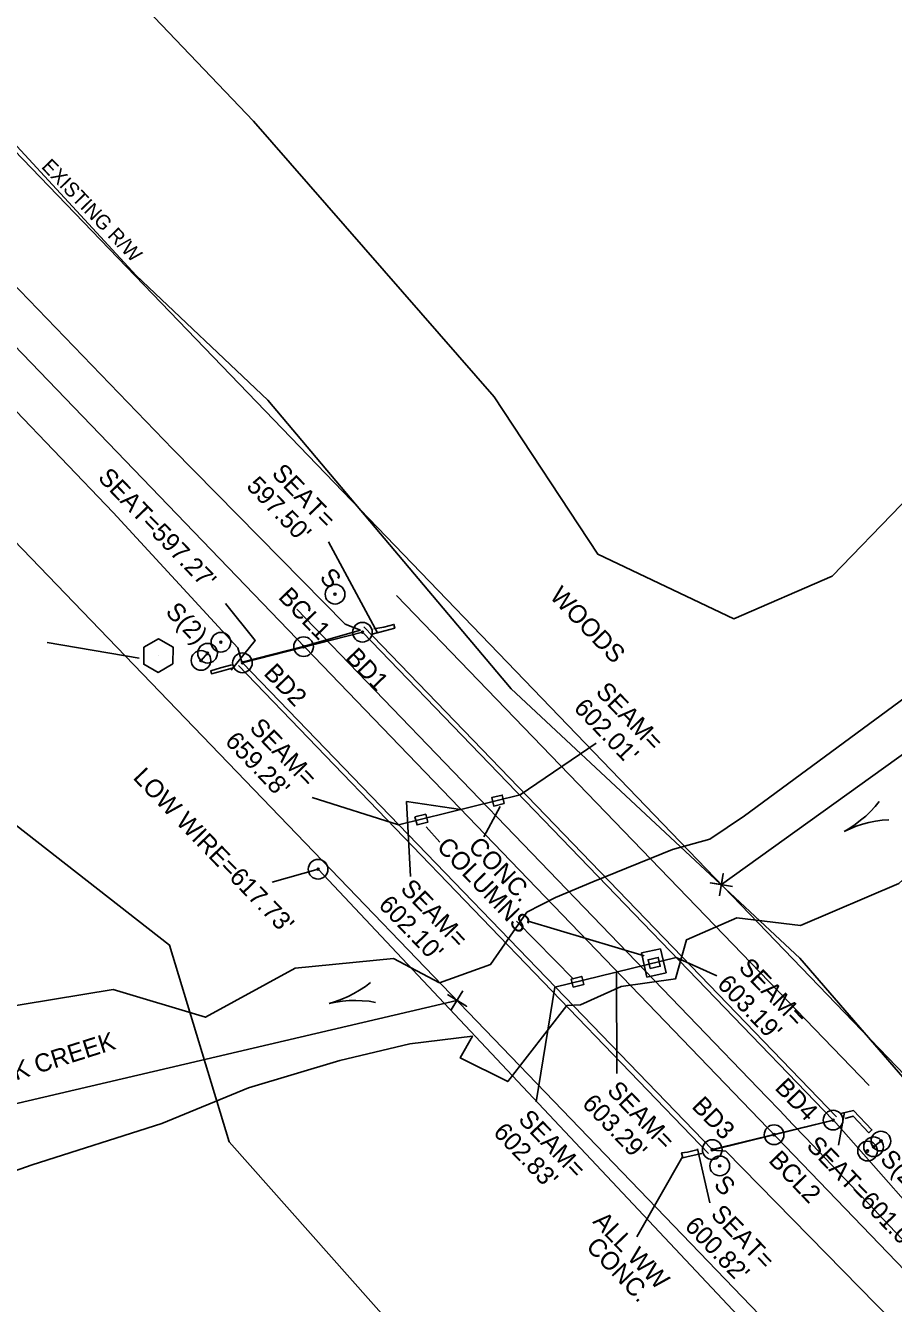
# Model space of a CAD drawing. Extents: x 1650735 to 1651711, y 679647 to 680525.
# Drawn here: x 1651160.8 to 1651353.2, y 680017 to 680300.3 of the extents above; entities that cross this region are included whole.
import ezdxf

# ---------------------------------------------------------------- set-up
doc = ezdxf.new("R2010")
doc.units = 0
for name, color, linetype in [('CTL Supplemental Horizontal and Vertical Leader', 7, 'Continuous'), ('Exist Horizontal Alignment', 7, 'Continuous'), ('Exist Hydro Jurisdictional Stream or Body of Water Mitigable Text', 7, 'Continuous'), ('Exist Hydro Stream Flow Arrow CELL', 7, 'Continuous'), ('Exist Hydro Stream or Body of Water', 7, 'Continuous'), ('Exist Hydro Stream or Body of Water Text', 7, 'Continuous'), ('Exist Other Culture Located Object CELL', 7, 'Continuous'), ('Exist Other Culture Located Object Leader', 7, 'Continuous'), ('Exist Other Culture Located Object Text', 7, 'Continuous'), ('Exist Other Culture Sign CELL', 7, 'Continuous'), ('Exist Other Culture Sign Text', 7, 'Continuous'), ('Exist Property Corner CELL', 7, 'Continuous'), ('Exist Property Line', 7, 'Continuous'), ('Exist Right of Way Line', 7, 'Continuous'), ('Exist Right of Way Line Text', 7, 'Continuous'), ('Exist Roads EOP', 7, 'Continuous'), ('Exist Roads EOP Other', 7, 'Continuous'), ('Exist Roads EOP Other Leader', 7, 'Continuous'), ('Exist Roads EOP Other Text', 7, 'Continuous'), ('Exist Structure Major Bridge Seam', 7, 'Continuous'), ('Exist Structure Major Bridge Seat Top Elevation', 7, 'Continuous'), ('Exist Structure Major Bridge WW', 7, 'Continuous'), ('Exist Structure Major Bridge WW Leader', 7, 'Continuous'), ('Exist Structure Major Bridge WW Text', 7, 'Continuous'), ('Exist Structure Major Deck Tunnel Box Culvert', 7, 'Continuous'), ('Exist Utilities Other Located Object CELL', 7, 'Continuous'), ('Exist Utilities Other Located Object Leader', 7, 'Continuous'), ('Exist Utilities Other Located Object Text', 7, 'Continuous'), ('Exist Utilities Power Pole Text', 7, 'Continuous'), ('Exist Vegetation Woods Line', 7, 'Continuous'), ('Exist Vegetation Woods Line Text', 7, 'Continuous')]:
    doc.layers.add(name, color=color, linetype=linetype)

msp = doc.modelspace()

# ---------------------------------------------------------------- linework, layer by layer
at = {"layer": 'CTL Supplemental Horizontal and Vertical Leader'}
msp.add_lwpolyline([(1651186.04, 680160.03), (1651165.62, 680163.51)], dxfattribs=at)
at = {"layer": 'Exist Horizontal Alignment'}
msp.add_line((1651012.3, 680380.99), (1651537.82, 679835.25), dxfattribs=at)
at = {"layer": 'Exist Hydro Jurisdictional Stream or Body of Water Mitigable Text'}
msp.add_line((1651190.29, 680160.59), (1651190.29, 680160.59), dxfattribs=at)
msp.add_lwpolyline([(1651187.06, 680162.47), (1651190.31, 680164.28), (1651193.56, 680162.49), (1651193.51, 680158.77), (1651190.26, 680156.88), (1651187.06, 680158.69)], close=True, dxfattribs=at)
at = {"layer": 'Exist Hydro Stream Flow Arrow CELL'}
for p, q in [((1651346.69, 680123.93), (1651346.69, 680123.93)), ((1651233.02, 680084.71), (1651233.02, 680084.71))]:
    msp.add_line(p, q, dxfattribs=at)
for points in [[(1651350.08, 680128.26), (1651349.17, 680127.11), (1651348.11, 680126.04), (1651347.06, 680125), (1651345.95, 680124.08), (1651344.76, 680123.19), (1651343.52, 680122.36), (1651342.26, 680121.62)], [(1651352.18, 680124.2), (1651350.72, 680124.12), (1651349.24, 680123.87), (1651347.79, 680123.61), (1651346.39, 680123.23), (1651344.98, 680122.77), (1651343.59, 680122.23), (1651342.26, 680121.62)], [(1651237.32, 680088.15), (1651236.17, 680087.24), (1651234.9, 680086.44), (1651233.63, 680085.68), (1651232.34, 680085.03), (1651230.98, 680084.45), (1651229.57, 680083.93), (1651228.17, 680083.5)], [(1651238.43, 680083.71), (1651236.99, 680083.96), (1651235.49, 680084.07), (1651234.02, 680084.15), (1651232.57, 680084.11), (1651231.09, 680083.99), (1651229.61, 680083.78), (1651228.17, 680083.5)]]:
    msp.add_lwpolyline(points, dxfattribs=at)
at = {"layer": 'Exist Hydro Stream or Body of Water'}
for points in [[(1651362.87, 680156.49), (1651320.19, 680125.07), (1651312.51, 680119.91), (1651304.26, 680117.62), (1651286.56, 680110.48), (1651278.28, 680106.96), (1651271.94, 680103.7)], [(1651409.21, 680154.78), (1651408.26, 680151.68), (1651378.34, 680131.92), (1651354.44, 680110.09), (1651332.62, 680100.74), (1651318.49, 680102.45), (1651307.34, 680097.61), (1651304.94, 680088.95), (1651292.83, 680087.22), (1651283.85, 680083.18)], [(1651271.94, 680103.7), (1651263.94, 680092.12), (1651252.63, 680088.06), (1651242.37, 680093.46), (1651220.61, 680091.28), (1651200.71, 680080.43), (1651180.24, 680086.55), (1651153.32, 680082.11), (1651107.96, 680068.84), (1651070.16, 680055.36)], [(1651283.85, 680083.18), (1651280.79, 680083.02), (1651267.73, 680066.16), (1651257.19, 680071.42), (1651259.9, 680076.25), (1651246.03, 680074.54), (1651230.51, 680070.83), (1651210.23, 680064.78), (1651191.09, 680056.85), (1651162.29, 680047.74), (1651122.74, 680033.79), (1651076.83, 680019.72)]]:
    msp.add_lwpolyline(points, dxfattribs=at)
at = {"layer": 'Exist Other Culture Located Object CELL'}
for centre, radius in [((1651235.53, 680165.78), 2.18), ((1651235.53, 680165.78), 0.24), ((1651222.46, 680162.57), 2.18), ((1651208.93, 680158.99), 2.18), ((1651222.46, 680162.57), 0.24), ((1651208.93, 680158.99), 0.24), ((1651339.85, 680057.63), 2.18), ((1651326.76, 680054.39), 2.18), ((1651339.85, 680057.63), 0.24), ((1651313.05, 680051.09), 2.18), ((1651326.76, 680054.39), 0.24), ((1651313.05, 680051.09), 0.24)]:
    msp.add_circle(centre, radius, dxfattribs=at)
at = {"layer": 'Exist Other Culture Located Object Leader'}
for p, q in [((1651238.86, 680165.65), (1651228.01, 680185.84)), ((1651270.45, 680129.72), (1651287.34, 680141.19)), ((1651243.5, 680123.07), (1651224.41, 680129.12)), ((1651305.09, 680093.68), (1651314.04, 680089.63)), ((1651291.85, 680090.48), (1651291.93, 680067.97)), ((1651278.14, 680087.13), (1651274, 680061.65)), ((1651342.37, 680059.38), (1651341.06, 680052.05)), ((1651309.76, 680051.24), (1651312.53, 680039.27))]:
    msp.add_line(p, q, dxfattribs=at)
for points in [[(1651206.42, 680157.39), (1651211.71, 680163.92), (1651205.16, 680172.13)], [(1651257.23, 680126.48), (1651245.29, 680128.24), (1651246.19, 680111.61)]]:
    msp.add_lwpolyline(points, dxfattribs=at)
at = {"layer": 'Exist Other Culture Sign CELL'}
for p, q in [((1651201.19, 680161.11), (1651199.74, 680159.51)), ((1651350.44, 680052.98), (1651348.8, 680051.71))]:
    msp.add_line(p, q, dxfattribs=at)
for centre, radius in [((1651229.45, 680174.21), 2.18), ((1651229.45, 680174.21), 0.24), ((1651204.14, 680163.56), 2.18), ((1651201.19, 680161.11), 2.18), ((1651204.14, 680163.56), 0.24), ((1651199.74, 680159.51), 2.18), ((1651201.19, 680161.11), 0.24), ((1651199.74, 680159.51), 0.24), ((1651347.48, 680050.77), 2.18), ((1651348.8, 680051.71), 2.18), ((1651350.44, 680052.98), 2.18), ((1651350.44, 680052.98), 0.24), ((1651314.71, 680047.49), 2.18), ((1651347.48, 680050.77), 0.24), ((1651348.8, 680051.71), 0.24), ((1651314.71, 680047.49), 0.24)]:
    msp.add_circle(centre, radius, dxfattribs=at)
at = {"layer": 'Exist Property Corner CELL'}
for p, q in [((1651315.07, 680109.82), (1651315.07, 680109.82)), ((1651256.47, 680084.17), (1651256.47, 680084.17))]:
    msp.add_line(p, q, dxfattribs=at)
for points in [[(1651314.67, 680107.35), (1651315.48, 680112.29), (1651315.07, 680109.82), (1651312.6, 680110.22), (1651317.54, 680109.42)], [(1651257.79, 680086.3), (1651255.15, 680082.05), (1651256.47, 680084.17), (1651258.6, 680082.86), (1651254.35, 680085.49)]]:
    msp.add_lwpolyline(points, dxfattribs=at)
at = {"layer": 'Exist Property Line'}
for p, q in [((1651599.36, 680314.21), (1651315.07, 680109.82)), ((1650934.59, 680008.86), (1651256.47, 680084.17))]:
    msp.add_line(p, q, dxfattribs=at)
at = {"layer": 'Exist Right of Way Line'}
for p, q in [((1651033.91, 680401.8), (1651559.43, 679856.06)), ((1650990.69, 680360.18), (1651516.21, 679814.44))]:
    msp.add_line(p, q, dxfattribs=at)
at = {"layer": 'Exist Roads EOP'}
for points in [[(1651019.58, 680387.57), (1651056.5, 680349), (1651091.07, 680312.89), (1651125.44, 680277.26), (1651159.55, 680241.49), (1651193.48, 680206.33), (1651231.7, 680167.56), (1651235.09, 680166.23)], [(1651005.03, 680374.4), (1651042.33, 680335.37), (1651077.42, 680299.13), (1651111.45, 680263.82), (1651145.42, 680228.7), (1651180.3, 680192.34), (1651207.92, 680162.35), (1651208.79, 680159.11)], [(1651208.79, 680159.11), (1651222.37, 680162.64), (1651235.09, 680166.23)], [(1651312.95, 680050.96), (1651326.69, 680054.39), (1651339.94, 680057.61)], [(1651339.94, 680057.61), (1651367.05, 680026.88), (1651401.64, 679990.76), (1651436.66, 679954.64), (1651471.24, 679919), (1651505.26, 679883.18), (1651544.65, 679842.12)], [(1651312.95, 680050.96), (1651316.09, 680050.72), (1651353.1, 680012.96), (1651388.04, 679976.97), (1651422.2, 679940.73), (1651457.05, 679905.32), (1651491.83, 679868.95), (1651530.99, 679828.38)]]:
    msp.add_lwpolyline(points, dxfattribs=at)
at = {"layer": 'Exist Roads EOP Other'}
for points in [[(1651266.93, 680127.79), (1651264.62, 680127.25), (1651264.18, 680129.12), (1651266.49, 680129.66)], [(1651247.16, 680124.83), (1651247.62, 680123.05), (1651250, 680123.66), (1651249.54, 680125.44)], [(1651301.61, 680095.63), (1651297.39, 680094.69), (1651298.58, 680089.35), (1651302.81, 680090.3)], [(1651299.27, 680091.23), (1651298.82, 680093.16), (1651301.09, 680093.69), (1651301.54, 680091.75)], [(1651282.23, 680087.07), (1651281.78, 680088.87), (1651284.14, 680089.47), (1651284.59, 680087.67)]]:
    msp.add_lwpolyline(points, close=True, dxfattribs=at)
at = {"layer": 'Exist Roads EOP Other Leader'}
for p, q in [((1651266.06, 680127.17), (1651262.43, 680120.43)), ((1651249.61, 680122.67), (1651252.65, 680119.27)), ((1651282.3, 680088.89), (1651269.64, 680101.71)), ((1651297.99, 680094.02), (1651272.27, 680101.72))]:
    msp.add_line(p, q, dxfattribs=at)
at = {"layer": 'Exist Structure Major Bridge Seam'}
for p, q in [((1651270.45, 680129.72), (1651243.5, 680123.07)), ((1651305.09, 680093.68), (1651278.14, 680087.13))]:
    msp.add_line(p, q, dxfattribs=at)
at = {"layer": 'Exist Structure Major Bridge WW'}
for points in [[(1651237.38, 680165.26), (1651240.51, 680166.07), (1651242.69, 680166.68), (1651242.5, 680167.51), (1651240.24, 680166.93), (1651238.03, 680166.49)], [(1651206.89, 680157.85), (1651204.26, 680157.13), (1651202.04, 680156.58), (1651201.89, 680157.21), (1651204.04, 680157.9), (1651206.6, 680158.55)], [(1651341.53, 680059.07), (1651344.39, 680059.74), (1651348.44, 680055.45), (1651347.76, 680054.83), (1651344.31, 680058.52), (1651342.55, 680058.01)], [(1651309.91, 680051.15), (1651307.58, 680050.55), (1651306.27, 680050.34), (1651306.5, 680049.28), (1651307.73, 680049.59), (1651310.73, 680050.23)]]:
    msp.add_lwpolyline(points, dxfattribs=at)
at = {"layer": 'Exist Structure Major Bridge WW Leader'}
msp.add_line((1651306.55, 680049.66), (1651296.35, 680031.79), dxfattribs=at)
at = {"layer": 'Exist Structure Major Deck Tunnel Box Culvert'}
msp.add_lwpolyline([(1651208.93, 680158.99), (1651313.05, 680051.09), (1651339.85, 680057.63), (1651235.53, 680165.78)], close=True, dxfattribs=at)
at = {"layer": 'Exist Utilities Other Located Object CELL'}
for radius in [2.18, 0.24]:
    msp.add_circle((1651225.7, 680113.25), radius, dxfattribs=at)
at = {"layer": 'Exist Utilities Other Located Object Leader'}
msp.add_line((1651225.7, 680113.25), (1651215.53, 680110.38), dxfattribs=at)
at = {"layer": 'Exist Utilities Power Pole Text'}
for p, q in [((1651347.81, 680065.31), (1651243.05, 680173.91)), ((1651221, 680170.86), (1651325.15, 680062.71)), ((1651340.61, 680058.37), (1651235.85, 680166.97)), ((1651208.03, 680158.38), (1651312.19, 680050.23)), ((1651225.7, 680113.25), (1651328.23, 680004.23))]:
    msp.add_line(p, q, dxfattribs=at)
msp.add_arc((1644826.06, 673836.82), 9000, 42.083008, 43.770098, dxfattribs=at)
at = {"layer": 'Exist Vegetation Woods Line'}
msp.add_line((1651332.44, 680093.53), (1651268.45, 680153.23), dxfattribs=at)
for points in [[(1651060.47, 680427.14), (1651110.65, 680381.51), (1651170.59, 680321.84), (1651211.4, 680279.05), (1651264.74, 680217.96)], [(1651268.45, 680153.23), (1651214.56, 680217.23), (1651185.34, 680244.85), (1651142.06, 680291.73), (1651110.43, 680323.33), (1651070.3, 680366.4), (1651038.41, 680400.33)], [(1650967.81, 680302.13), (1650989.98, 680311.82), (1651003.7, 680297.93), (1651028.47, 680259.93), (1651064.77, 680218.76), (1651095.8, 680179.69), (1651142.63, 680135.48), (1651192.79, 680096.42), (1651205.99, 680052.81)], [(1651264.74, 680217.96), (1651287.7, 680183.05), (1651317.85, 680168.78), (1651339.66, 680178.23), (1651416.09, 680257.26)], [(1651533.77, 680151.79), (1651500.2, 680143.28), (1651448.94, 680108.35), (1651428.64, 680087.41), (1651415.56, 680062.68), (1651389.29, 680041.87), (1651370.95, 680049.08), (1651332.44, 680093.53)], [(1651205.99, 680052.81), (1651250.75, 680002.32), (1651325.09, 679941.65), (1651395.44, 679858.06), (1651436.98, 679824.06), (1651426.61, 679814.61)]]:
    msp.add_lwpolyline(points, dxfattribs=at)

# ---------------------------------------------------------------- texts
at = {"layer": 'Exist Hydro Stream or Body of Water Text'}
msp.add_text('LICK CREEK', height=4, rotation=17.5647, dxfattribs=at).set_placement((1651150.76, 680063.87))
at = {"layer": 'Exist Other Culture Located Object Text'}
for s, p in [('BCL1', (1651216.66, 680173.4)), ('BD1', (1651231.55, 680159.96)), ('BD2', (1651213.43, 680156.49)), ('BD4', (1651326.72, 680064.61)), ('BD3', (1651308.3, 680060.52)), ('BCL2', (1651325.33, 680048.52))]:
    msp.add_text(s, height=4, rotation=313.9188, dxfattribs=at).set_placement(p)
at = {"layer": 'Exist Other Culture Sign Text'}
for s, p in [('S', (1651225.81, 680177.69)), ('S(2)', (1651191.67, 680170.09)), ('S(2)', (1651350.05, 680048.76)), ('S', (1651313.19, 680043.11))]:
    msp.add_text(s, height=4, rotation=313.9188, dxfattribs=at).set_placement(p)
at = {"layer": 'Exist Right of Way Line Text'}
msp.add_text('EXISTING R/W', height=3.2, rotation=313.9188, dxfattribs=at).set_placement((1651164.19, 680268.81))
at = {"layer": 'Exist Roads EOP Other Text'}
for s, p in [('COLUMNS', (1651251.76, 680118.01)), ('CONC.', (1651258.73, 680118.08))]:
    msp.add_text(s, height=4, rotation=313.9188, dxfattribs=at).set_placement(p)
at = {"layer": 'Exist Structure Major Bridge Seat Top Elevation'}
for s, p in [('SEAT=', (1651215.21, 680200.78)), ("SEAT=597.27'", (1651176.68, 680199.86)), ("597.50'", (1651209.6, 680197.96)), ('SEAM=', (1651287.02, 680152.37)), ("602.01'", (1651282.15, 680148.77)), ('SEAM=', (1651210.28, 680144.39)), ("659.28'", (1651204.85, 680141.39)), ('SEAM=', (1651243.74, 680108.7)), ("602.10'", (1651238.87, 680105.11)), ('SEAM=', (1651318.69, 680091.23)), ("603.19'", (1651313.93, 680087.52)), ('SEAM=', (1651289.54, 680063.95)), ("603.29'", (1651284, 680061.06)), ('SEAM=', (1651269.85, 680057.6)), ("602.83'", (1651264.31, 680054.71)), ("SEAT=601.09'", (1651333.73, 680051.75)), ('SEAT=', (1651312.52, 680036.55)), ("600.82'", (1651306.73, 680033.91))]:
    msp.add_text(s, height=4, rotation=313.9188, dxfattribs=at).set_placement(p)
at = {"layer": 'Exist Structure Major Bridge WW Text'}
for s, p in [('ALL WW', (1651286.38, 680035)), ('CONC.', (1651284.87, 680029.35))]:
    msp.add_text(s, height=4, rotation=313.9188, dxfattribs=at).set_placement(p)
at = {"layer": 'Exist Utilities Other Located Object Text'}
msp.add_text("LOW WIRE=617.73'", height=4, rotation=313.9188, dxfattribs=at).set_placement((1651184.47, 680133.4))
at = {"layer": 'Exist Vegetation Woods Line Text'}
msp.add_text('WOODS', height=4, rotation=313.9188, dxfattribs=at).set_placement((1651276.83, 680173.57))

doc.saveas('drawing.dxf')
